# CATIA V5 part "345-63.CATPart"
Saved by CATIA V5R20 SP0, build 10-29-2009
Part number: 345-63
Definition: NONE
Nomenclature: 345-63
Source: Unknown
Description: 345-63
Bounding box of the stored display mesh (mm): x 0 to 99, y -60 to 60, z -60 to 60
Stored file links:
  C:\Users\Utente\Desktop\IO LAVORO\3D X SITO CF\X SITO\345-346\345-63.CATPart
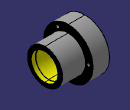
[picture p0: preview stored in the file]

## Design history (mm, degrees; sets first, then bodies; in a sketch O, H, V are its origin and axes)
Body1 "345-63" (main body)
  Solid1: solid without history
